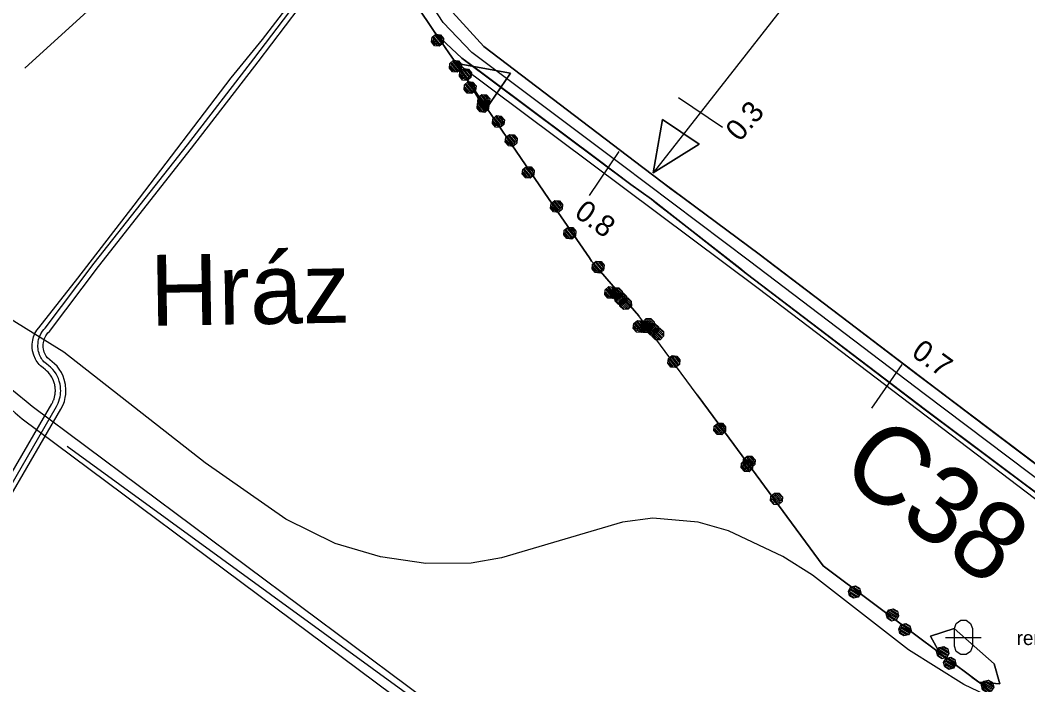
# Model space of a CAD drawing. Extents: x -645676 to -642474, y -1077513 to -1072613.
# Drawn here: x -645445.2 to -645160.5, y -1075082.2 to -1074894.5 of the extents above; entities that cross this region are included whole.
import ezdxf

# ---------------------------------------------------------------- set-up
doc = ezdxf.new("R2010")
doc.units = 0
for name, color, linetype in [('_cesty_Slatinany', 7, 'Continuous'), ('ELEKTRO', 7, 'Continuous'), ('KRAJ_ZELEN_STAV', 7, 'Continuous'), ('Krajinn__zele____popis___stav', 7, 'Continuous'), ('KULTURY_STAV', 7, 'Continuous'), ('KULTURY_ZNACKY', 7, 'Continuous'), ('NOVY_STAV_SLATINANY', 7, 'Continuous'), ('OBVOD_PU', 7, 'Continuous'), ('OSA', 7, 'Continuous'), ('PC_MIMO_OBV', 7, 'Continuous'), ('PC_NAVRH', 7, 'Continuous'), ('PC_POPIS_NAVRH', 7, 'Continuous'), ('PC_STAN_NAVRH', 7, 'Continuous'), ('PRVKY_PSZ', 7, 'Continuous'), ('SPRAV_HR_STAV', 7, 'Continuous'), ('Vodn__plocha___st_vaj_c_', 7, 'Continuous'), ('Vodn__tok', 7, 'Continuous'), ('VRSTEVNICE', 7, 'Continuous')]:
    doc.layers.add(name, color=color, linetype=linetype)

# ---------------------------------------------------------------- blocks, each defined once
blk = doc.blocks.new('$944')
blk.add_line((0, 1.5), (0, -1.5))
blk = doc.blocks.new('$920')
for points in [[(0, 0), (-2.8, 1.25), (-2.8, -1.25), (0, 0)], [(-2.8, 1.25), (0, 0), (-2.8, -1.25), (-2.8, 1.25)]]:
    blk.add_lwpolyline(points)
blk = doc.blocks.new('3$1600')
for points in [[(-0.5, 1.5), (-0.4, 1.79), (-0.15, 1.97), (0.16, 1.97), (0.41, 1.79), (0.51, 1.5), (0.51, 0.5), (0.41, 0.21), (0.16, 0.03), (-0.15, 0.03), (-0.4, 0.21), (-0.5, 0.5), (-0.5, 1.5)], [(-1, 1), (0.27, 1), (1, 1)]]:
    blk.add_lwpolyline(points)
blk = doc.blocks.new('2$0620')
for points in [[(-1.07, 0.32), (-0.88, 0.13), (-0.88, -0.14), (-1.07, -0.33), (-1.34, -0.33), (-1.53, -0.14), (-1.53, 0.13), (-1.34, 0.32), (-1.07, 0.32), (-1.08, 0.28), (-1.32, 0.28), (-1.4, 0.2), (-1, 0.2), (-0.92, 0.12), (-1.48, 0.12), (-1.48, 0.04), (-0.92, 0.04), (-0.92, -0.04), (-1.48, -0.04), (-1.48, -0.12), (-0.92, -0.12), (-1, -0.2), (-1.4, -0.2), (-1.32, -0.28), (-1.08, -0.28)], [(1.43, 0.32), (1.62, 0.13), (1.62, -0.14), (1.43, -0.33), (1.16, -0.33), (0.97, -0.14), (0.97, 0.13), (1.16, 0.32), (1.43, 0.32), (1.4, 0.28), (1.16, 0.28), (1.08, 0.2), (1.48, 0.2), (1.56, 0.12), (1, 0.12), (1, 0.04), (1.56, 0.04), (1.56, -0.04), (1, -0.04), (1, -0.12), (1.56, -0.12), (1.48, -0.2), (1.08, -0.2), (1.16, -0.28), (1.4, -0.28)]]:
    blk.add_lwpolyline(points)

msp = doc.modelspace()

# ---------------------------------------------------------------- linework, layer by layer
at = {"layer": '_cesty_Slatinany'}
for points in [[(-645453.69, -1074993.83), (-645443.47, -1075002.14), (-645441.79, -1075003.56), (-645199.23, -1075184.27)], [(-645456.24, -1074996.92), (-645446.57, -1075005.41), (-645444.59, -1075007.09), (-645201.92, -1075187.88)]]:
    msp.add_lwpolyline(points, dxfattribs=at)
at = {"layer": 'ELEKTRO'}
msp.add_line((-645421.96, -1074888.09), (-645443.87, -1074908.08), dxfattribs=at)
at = {"layer": 'KRAJ_ZELEN_STAV'}
msp.add_lwpolyline([(-645188.06, -1075068.49), (-645181.3, -1075066.36), (-645170.04, -1075076.32), (-645168.42, -1075081.92), (-645174.41, -1075081.48), (-645185.4, -1075073.26), (-645188.06, -1075068.49)], dxfattribs=at)
at = {"layer": 'KULTURY_STAV'}
for points in [[(-645130.94, -1075048.32), (-645189.48, -1075004.6), (-645240.04, -1074966.05), (-645241.91, -1074964.59), (-645262.67, -1074948.34), (-645265.47, -1074946.16), (-645266.86, -1074945.07), (-645272.63, -1074940.93), (-645282.31, -1074933.68), (-645299.39, -1074920.89), (-645315.49, -1074908.83), (-645320.35, -1074905.19), (-645327.69, -1074898.44), (-645328.21, -1074897.69), (-645333.18, -1074890.27)], [(-645323.01, -1074892.28), (-645314.19, -1074901.9), (-645269.27, -1074936.11), (-645263.44, -1074940.56), (-645261.38, -1074942.09), (-645257.95, -1074944.63), (-645236.45, -1074960.57), (-645232, -1074963.95), (-645212.92, -1074978.48), (-645191.76, -1074994.58), (-645186.18, -1074998.83), (-645172.85, -1075008.89), (-645153.28, -1075023.65)], [(-645153.28, -1075023.65), (-645172.85, -1075008.89), (-645186.18, -1074998.83), (-645191.76, -1074994.58), (-645212.92, -1074978.48), (-645232, -1074963.95), (-645236.45, -1074960.57), (-645257.95, -1074944.63), (-645261.38, -1074942.09), (-645263.44, -1074940.56), (-645269.27, -1074936.11), (-645314.19, -1074901.9), (-645323.01, -1074892.28)], [(-645328.21, -1074897.69), (-645327.69, -1074898.44), (-645326.2, -1074899.81), (-645320.35, -1074905.19), (-645315.49, -1074908.83), (-645299.39, -1074920.89), (-645282.31, -1074933.68), (-645272.63, -1074940.93), (-645266.86, -1074945.07), (-645265.47, -1074946.16), (-645262.67, -1074948.34), (-645241.91, -1074964.59), (-645240.04, -1074966.05), (-645189.48, -1075004.6), (-645130.94, -1075048.32), (-645120.53, -1075056.18), (-645118.8, -1075057.49), (-645116.58, -1075059.17), (-645111.97, -1075062.65), (-645103.54, -1075069.02), (-645091.1, -1075078.42), (-645086.59, -1075081.86), (-645069.93, -1075094.6)], [(-645172.22, -1075083.12), (-645176.31, -1075080.06), (-645174.41, -1075081.48), (-645168.42, -1075081.92), (-645170.04, -1075076.32), (-645181.3, -1075066.36), (-645188.06, -1075068.49), (-645185.4, -1075073.25), (-645191.42, -1075068.75), (-645204.1, -1075059.26), (-645218.32, -1075048.62), (-645246.19, -1075010.78), (-645253.89, -1075000.33), (-645270.37, -1074977.96), (-645281.25, -1074965.48), (-645282.5, -1074964.02), (-645283.73, -1074962.59), (-645284.38, -1074961.65), (-645295.91, -1074944.82), (-645307.67, -1074927.67), (-645320.44, -1074909.03), (-645324.08, -1074903.72), (-645328.21, -1074897.69)], [(-645181.3, -1075066.36), (-645170.04, -1075076.32), (-645168.42, -1075081.92), (-645174.41, -1075081.48), (-645176.31, -1075080.06), (-645185.4, -1075073.25), (-645188.06, -1075068.49), (-645181.3, -1075066.36)]]:
    msp.add_lwpolyline(points, dxfattribs=at)
at = {"layer": 'NOVY_STAV_SLATINANY'}
for points in [[(-645484.43, -1075085.71), (-645436.23, -1075002.88), (-645436.11, -1075002.67), (-645436.04, -1075002.54), (-645435.96, -1075002.38), (-645435.88, -1075002.21), (-645435.8, -1075002.04), (-645435.74, -1075001.87), (-645435.67, -1075001.69), (-645435.57, -1075001.42), (-645435.52, -1075001.26), (-645435.47, -1075001.06), (-645435.41, -1075000.83), (-645435.35, -1075000.58), (-645435.32, -1075000.41), (-645435.29, -1075000.17), (-645435.26, -1074999.94), (-645435.23, -1074999.71), (-645435.22, -1074999.5), (-645435.21, -1074999.34), (-645435.21, -1074999.12), (-645435.21, -1074998.9), (-645435.22, -1074998.69), (-645435.24, -1074998.42), (-645435.26, -1074998.21), (-645435.28, -1074998.06), (-645435.32, -1074997.81), (-645435.36, -1074997.61), (-645435.4, -1074997.41), (-645435.45, -1074997.22), (-645435.52, -1074996.96), (-645435.74, -1074996.39), (-645436.03, -1074995.66), (-645436.2, -1074995.33), (-645436.57, -1074994.78), (-645436.83, -1074994.43), (-645437.26, -1074993.92), (-645437.71, -1074993.52), (-645437.97, -1074993.29), (-645438.67, -1074992.72), (-645439.37, -1074992.15), (-645439.74, -1074991.76), (-645440.07, -1074991.37), (-645440.33, -1074990.99), (-645440.59, -1074990.63), (-645440.79, -1074990.24), (-645441.32, -1074989.16), (-645441.64, -1074987.88), (-645441.76, -1074987.09), (-645441.74, -1074985.98), (-645441.61, -1074984.87), (-645441.35, -1074983.92), (-645440.98, -1074983), (-645440.45, -1074982.09), (-645439.84, -1074981.4), (-645428.84, -1074967.34), (-645412.94, -1074946.74), (-645385.56, -1074910.83), (-645376.69, -1074899.99), (-645351.7, -1074867.27)], [(-645457.73, -1075045.8), (-645433.63, -1075004.39), (-645433, -1075003.12), (-645432.64, -1075002.18), (-645432.42, -1075001.1), (-645432.27, -1075000.24), (-645432.22, -1074998.91), (-645432.31, -1074997.4), (-645432.68, -1074996.01), (-645432.98, -1074995.09), (-645433.51, -1074994), (-645434.1, -1074993.05), (-645434.72, -1074992.21), (-645435.42, -1074991.53), (-645436.07, -1074990.97), (-645436.77, -1074990.4), (-645437.47, -1074989.83), (-645437.77, -1074989.41), (-645438.01, -1074988.99), (-645438.18, -1074988.65), (-645438.33, -1074988.23), (-645438.46, -1074987.81), (-645438.56, -1074987.42), (-645438.62, -1074986.9), (-645438.64, -1074986.42), (-645438.62, -1074986), (-645438.58, -1074985.6), (-645438.48, -1074985.13), (-645438.39, -1074984.79), (-645438.26, -1074984.42), (-645438.09, -1074984.02), (-645437.9, -1074983.66), (-645437.73, -1074983.38), (-645437.29, -1074982.8), (-645436.9, -1074982.4), (-645423.03, -1074964.06), (-645396.74, -1074930.61), (-645377.93, -1074906.3), (-645366.33, -1074890.99)]]:
    msp.add_lwpolyline(points, dxfattribs=at)
at = {"layer": 'OBVOD_PU'}
msp.add_lwpolyline([(-645172.22, -1075083.12), (-645191.42, -1075068.75), (-645204.1, -1075059.26), (-645218.32, -1075048.62), (-645246.19, -1075010.78), (-645253.89, -1075000.33), (-645270.37, -1074977.96), (-645281.25, -1074965.48), (-645282.5, -1074964.02), (-645283.73, -1074962.59), (-645284.38, -1074961.65), (-645295.91, -1074944.82), (-645307.67, -1074927.67), (-645320.44, -1074909.03), (-645324.08, -1074903.72), (-645328.21, -1074897.69), (-645333.18, -1074890.27)], dxfattribs=at)
at = {"layer": 'OSA'}
msp.add_lwpolyline([(-645462.77, -1075051.83), (-645434.93, -1075003.63), (-645434.7, -1075003.24), (-645434.44, -1075002.67), (-645434.24, -1075002.15), (-645434.03, -1075001.48), (-645433.88, -1075000.88), (-645433.77, -1075000.28), (-645433.73, -1074999.78), (-645433.7, -1074999.22), (-645433.72, -1074998.67), (-645433.79, -1074997.94), (-645433.88, -1074997.3), (-645434.11, -1074996.46), (-645434.36, -1074995.74), (-645434.64, -1074995.12), (-645435.01, -1074994.41), (-645435.46, -1074993.77), (-645435.9, -1074993.21), (-645436.59, -1074992.49), (-645437.02, -1074992.13), (-645437.72, -1074991.56), (-645438.42, -1074990.99), (-645438.66, -1074990.75), (-645438.89, -1074990.44), (-645439.11, -1074990.1), (-645439.3, -1074989.76), (-645439.51, -1074989.36), (-645439.65, -1074989.03), (-645439.82, -1074988.55), (-645439.94, -1074988.11), (-645440.02, -1074987.7), (-645440.1, -1074987.27), (-645440.13, -1074986.78), (-645440.14, -1074986.37), (-645440.11, -1074985.83), (-645440.04, -1074985.25), (-645439.93, -1074984.7), (-645439.79, -1074984.25), (-645439.59, -1074983.72), (-645439.32, -1074983.13), (-645438.86, -1074982.38), (-645438.44, -1074981.85), (-645438.1, -1074981.5), (-645424.22, -1074963.14), (-645397.92, -1074929.68), (-645379.12, -1074905.39), (-645367.51, -1074890.08)], dxfattribs=at)
at = {"layer": 'PC_MIMO_OBV'}
msp.add_lwpolyline([(-645431.84, -1075014.81), (-645330.83, -1075088.35), (-645200.48, -1075185.92)], dxfattribs=at)
at = {"layer": 'PC_NAVRH'}
for points in [[(-645021.99, -1074891.99), (-645037.6, -1074895.68), (-645059.4, -1074892.54), (-645113.44, -1074873.13), (-645139.31, -1074861.49), (-645174.24, -1074826.29), (-645176.85, -1074825.42), (-645179.43, -1074826.52), (-645194.09, -1074845.22), (-645266.33, -1074937.66)], [(-644615.94, -1075324.38), (-644614.35, -1075298.06), (-644618.37, -1075293.21), (-644622.69, -1075291.24), (-644738.79, -1075265.15), (-644794.9, -1075254.19), (-644881.17, -1075235.85), (-644890.64, -1075231.29), (-644935.93, -1075197.93), (-645029.58, -1075127.01), (-645122.98, -1075056.71), (-645236.69, -1074970.28), (-645321.72, -1074906.75)]]:
    msp.add_lwpolyline(points, dxfattribs=at)
at = {"layer": 'SPRAV_HR_STAV'}
for p, q in [((-645333.18, -1074890.27), (-645328.21, -1074897.69)), ((-645328.21, -1074897.69), (-645324.08, -1074903.72)), ((-645324.08, -1074903.72), (-645320.44, -1074909.03)), ((-645320.44, -1074909.03), (-645307.67, -1074927.67)), ((-645307.67, -1074927.67), (-645295.91, -1074944.82)), ((-645295.91, -1074944.82), (-645284.38, -1074961.65)), ((-645284.38, -1074961.65), (-645283.73, -1074962.59)), ((-645283.73, -1074962.59), (-645282.5, -1074964.02)), ((-645282.5, -1074964.02), (-645281.25, -1074965.48)), ((-645281.25, -1074965.48), (-645270.37, -1074977.96)), ((-645253.89, -1075000.33), (-645270.37, -1074977.96)), ((-645253.89, -1075000.33), (-645246.19, -1075010.78)), ((-645246.19, -1075010.78), (-645218.32, -1075048.62)), ((-645218.32, -1075048.62), (-645204.1, -1075059.26)), ((-645204.1, -1075059.26), (-645191.42, -1075068.75)), ((-645191.42, -1075068.75), (-645172.22, -1075083.12))]:
    msp.add_line(p, q, dxfattribs=at)
at = {"layer": 'Vodn__plocha___st_vaj_c_'}
for points in [[(-645320.35, -1074905.19), (-645327.69, -1074898.44), (-645328.21, -1074897.69), (-645333.18, -1074890.27), (-645343.74, -1074873.94), (-645358.89, -1074850.26), (-645374.16, -1074826.22), (-645368.02, -1074824.22), (-645353.57, -1074846.73), (-645323.01, -1074892.28), (-645314.19, -1074901.9), (-645269.27, -1074936.11), (-645263.44, -1074940.56), (-645236.45, -1074960.57), (-645186.18, -1074998.83), (-645127.03, -1075043.46), (-645119.22, -1075048.8), (-645115.32, -1075053.06), (-645110.78, -1075056.48), (-645087.88, -1075073.72), (-645037.68, -1075112.27)], [(-645127.03, -1075043.46), (-645186.18, -1074998.83), (-645236.45, -1074960.57), (-645263.44, -1074940.56), (-645269.27, -1074936.11), (-645314.19, -1074901.9), (-645323.01, -1074892.28), (-645353.57, -1074846.73), (-645368.02, -1074824.22), (-645374.16, -1074826.22), (-645358.89, -1074850.26), (-645343.74, -1074873.94), (-645333.18, -1074890.27), (-645328.21, -1074897.69), (-645327.69, -1074898.44), (-645320.35, -1074905.19), (-645272.63, -1074940.93), (-645266.86, -1074945.07), (-645240.04, -1074966.05), (-645189.47, -1075004.6), (-645130.94, -1075048.32)], [(-645040.7, -1075116.95), (-645091.1, -1075078.42), (-645130.94, -1075048.32), (-645189.47, -1075004.6), (-645240.04, -1074966.05), (-645266.86, -1074945.07), (-645272.63, -1074940.93), (-645320.35, -1074905.19)]]:
    msp.add_lwpolyline(points, dxfattribs=at)
at = {"layer": 'Vodn__tok'}
msp.add_lwpolyline([(-644737.28, -1075262.07), (-644790.63, -1075250.71), (-644852.68, -1075237.9), (-644879.87, -1075231.93), (-644887.46, -1075228.4), (-644913.43, -1075209.05), (-644922.62, -1075202.32), (-644931.59, -1075195.91), (-644942.63, -1075187.1), (-644967.94, -1075167.74), (-644997, -1075145.82), (-645040.36, -1075114.96), (-645089.98, -1075076.71), (-645130.46, -1075044.8), (-645189.79, -1075000.02), (-645239.14, -1074962.61), (-645275.37, -1074935.26), (-645317.56, -1074903.59), (-645325.71, -1074895.16), (-645357.55, -1074846.07), (-645371.25, -1074825.24)], dxfattribs=at)
at = {"layer": 'VRSTEVNICE'}
msp.add_lwpolyline([(-645164.2, -1075088.99), (-645178.59, -1075082.15), (-645194.25, -1075072.32), (-645221.31, -1075051.25), (-645229.72, -1075045.98), (-645245.1, -1075038.71), (-645253.64, -1075036.29), (-645266.46, -1075035.15), (-645275.01, -1075036.29), (-645309.19, -1075046.4), (-645317.73, -1075047.83), (-645330.55, -1075047.97), (-645343.37, -1075046.12), (-645356.19, -1075042.27), (-645370.14, -1075035.44), (-645392.93, -1075019.49), (-645432.81, -1074988.29), (-645470.27, -1074965.08)], dxfattribs=at)

# ---------------------------------------------------------------- block references
at = {"layer": 'KULTURY_ZNACKY', "xscale": 5, "yscale": 5}
msp.add_blockref('3$1600', (-645178.74, -1075073.84), dxfattribs=at)
at = {"layer": 'PC_STAN_NAVRH', "xscale": 5, "yscale": 5}
for name, p, rotation in [('$920', (-645321.72, -1074906.75), 145.733625), ('$944', (-645253.01, -1074920.62), -123.954564), ('$920', (-645266.33, -1074937.66), -123.954564), ('$944', (-645280.15, -1074937.8), 145.733625), ('$944', (-645200.27, -1074997.96), 145.249766)]:
    msp.add_blockref(name, p, dxfattribs=dict(at, rotation=rotation))
at = {"layer": 'SPRAV_HR_STAV'}
for p, xscale, yscale, rotation in [((-645323.44, -1074904.81), 5, 5, -50.88280600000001), ((-645318.32, -1074912.13), 4.999999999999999, 5, -50.279487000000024), ((-645314.19, -1074918.15), 5, 5, -50.25608200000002), ((-645310.55, -1074923.47), 5, 5, -50.27248200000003), ((-645297.77, -1074942.1), 5, 5, -50.247548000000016), ((-645286.02, -1074959.26), 5.000000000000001, 4.999999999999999, -50.272455), ((-645274.43, -1074976.04), 5, 5, -50.01916300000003), ((-645272.32, -1074975.86), 5, 5, -43.87711799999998), ((-645271.12, -1074977.31), 5, 5, -44.01060200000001), ((-645269.75, -1074978.67), 5, 5, -43.48884099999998), ((-645264.27, -1074986.24), 5, 5, 128.584845), ((-645243.51, -1075014.42), 5, 5, -48.26822), ((-645235.81, -1075024.87), 4.999999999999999, 5.000000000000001, -48.28031200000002), ((-645204.31, -1075059.1), 5, 5, -31.164555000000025), ((-645190.09, -1075069.75), 5, 4.999999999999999, -31.171310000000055), ((-645177.41, -1075079.24), 5, 4.999999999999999, -31.171866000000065)]:
    msp.add_blockref('2$0620', p, dxfattribs=dict(at, xscale=xscale, yscale=yscale, rotation=rotation))

# ---------------------------------------------------------------- texts
at = {"layer": 'Krajinn__zele____popis___stav'}
msp.add_text('remízek', height=4, dxfattribs=at).set_placement((-645163.69, -1075070.99))
at = {"layer": 'PC_POPIS_NAVRH'}
msp.add_text('C38', height=22, rotation=323.091, dxfattribs=at).set_placement((-645214.46, -1075022.53))
at = {"layer": 'PC_STAN_NAVRH'}
for s, rotation, p in [('0.3', 49.504, (-645241.88, -1074929.08)), ('0.8', 324.008, (-645288.94, -1074949.68)), ('0.7', 324.008, (-645193.72, -1074989.12))]:
    msp.add_text(s, height=6, rotation=rotation, dxfattribs=at).set_placement(p)
at = {"layer": 'PRVKY_PSZ'}
msp.add_text('Hráz ', height=20, rotation=0.917, dxfattribs=at).set_placement((-645408.32, -1074980.82))

doc.saveas('drawing.dxf')
